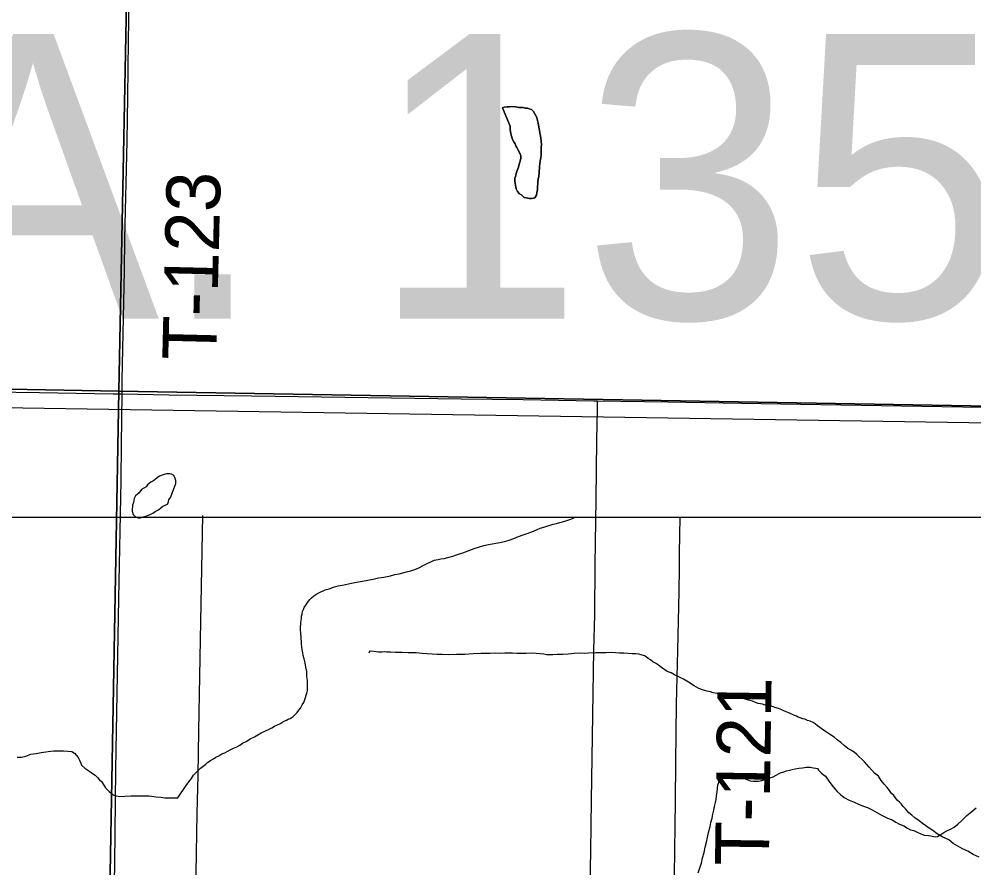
# Model space of a CAD drawing. Extents: x 2.4 to 73.1, y 4.5 to 25.6.
# Drawn here: x 43.971 to 44.474, y 19.357 to 19.804 of the extents above; entities that cross this region are included whole.
import ezdxf

# ---------------------------------------------------------------- set-up
doc = ezdxf.new("R2010")
doc.units = 0
for name, color, linetype in [('GM_X_County_Road', 7, 'Continuous'), ('GM_X_Minor_Lake', 7, 'Continuous'), ('GM_X_Minor_River', 7, 'Continuous'), ('GM_X_Section', 7, 'Continuous'), ('GM_X_State_Route', 7, 'Continuous'), ('GM_X_Township_Road', 7, 'Continuous'), ('GM_X_Township_Road_Text', 7, 'Continuous'), ('SH_Text', 7, 'Continuous')]:
    doc.layers.add(name, color=color, linetype=linetype)

msp = doc.modelspace()

# ---------------------------------------------------------------- linework, layer by layer
at = {"layer": 'GM_X_County_Road'}
msp.add_lwpolyline([(44.01702, 19.10105), (44.01746, 19.1365), (44.01805, 19.15825), (44.01831, 19.1769), (44.01926, 19.22506), (44.01963, 19.24681), (44.02, 19.27167), (44.02064, 19.3043), (44.02109, 19.33071), (44.02153, 19.35868), (44.02219, 19.40841), (44.02378, 19.49852), (44.02492, 19.56067), (44.02516, 19.57932), (44.02545, 19.60622)], dxfattribs=at)
at = {"layer": 'GM_X_Minor_Lake'}
for points in [[(44.24431, 19.71562), (44.24453, 19.71676), (44.24456, 19.71809), (44.24459, 19.71942), (44.24501, 19.72093), (44.24523, 19.72244), (44.24526, 19.72377), (44.24529, 19.72491), (44.24531, 19.72605), (44.24553, 19.72737), (44.24576, 19.72908), (44.24599, 19.73059), (44.24621, 19.73192), (44.24624, 19.73324), (44.24627, 19.73476), (44.2463, 19.73609), (44.24634, 19.73761), (44.24618, 19.73932), (44.24603, 19.74103), (44.2457, 19.74294), (44.24469, 19.74885), (44.24434, 19.75019), (44.24417, 19.75114), (44.24381, 19.7521), (44.24308, 19.75345), (44.24217, 19.75499), (44.24124, 19.75596), (44.23992, 19.75637), (44.23898, 19.75677), (44.23784, 19.75679), (44.2367, 19.75701), (44.23442, 19.75706), (44.23272, 19.75748), (44.23063, 19.75753), (44.22948, 19.75736), (44.22834, 19.75739), (44.22682, 19.75723), (44.22586, 19.75687)], [(44.22586, 19.75687), (44.22682, 19.75723), (44.22834, 19.75739), (44.22948, 19.75736), (44.23063, 19.75753), (44.23272, 19.75748), (44.23442, 19.75706), (44.2367, 19.75701), (44.23784, 19.75679), (44.23898, 19.75677), (44.23992, 19.75637), (44.24124, 19.75596), (44.24217, 19.75499), (44.24308, 19.75345), (44.24381, 19.7521), (44.24417, 19.75114), (44.24434, 19.75019), (44.24469, 19.74885), (44.2457, 19.74294), (44.24603, 19.74103), (44.24618, 19.73932), (44.24634, 19.73761), (44.2463, 19.73609), (44.24627, 19.73476), (44.24624, 19.73324), (44.24621, 19.73192), (44.24599, 19.73059), (44.24576, 19.72908), (44.24553, 19.72737), (44.24531, 19.72605), (44.24529, 19.72491), (44.24526, 19.72377), (44.24523, 19.72244), (44.24501, 19.72093), (44.24459, 19.71942), (44.24456, 19.71809), (44.24453, 19.71676), (44.24431, 19.71562), (44.24428, 19.71392), (44.24405, 19.7124), (44.24383, 19.71089), (44.24285, 19.70958), (44.24113, 19.70924), (44.24017, 19.70907), (44.23828, 19.70949), (44.23734, 19.7097), (44.23603, 19.71087), (44.23491, 19.71166), (44.2338, 19.71282), (44.23307, 19.71417), (44.2329, 19.71512), (44.2324, 19.71836), (44.23243, 19.71988), (44.23265, 19.72083), (44.23306, 19.72215), (44.23327, 19.72309), (44.23388, 19.72479), (44.23428, 19.72573), (44.23469, 19.72724), (44.23511, 19.72875), (44.23553, 19.73045), (44.23555, 19.73158), (44.23502, 19.73312), (44.23392, 19.73504), (44.23337, 19.736), (44.23282, 19.73696), (44.23246, 19.73792), (44.23192, 19.73907), (44.23119, 19.74023), (44.23083, 19.74138), (44.23048, 19.74253), (44.23031, 19.74348), (44.22997, 19.74538), (44.22999, 19.74633), (44.22983, 19.74729), (44.22586, 19.75687)], [(44.22586, 19.75687), (44.22983, 19.74729), (44.22999, 19.74633), (44.22997, 19.74538), (44.23031, 19.74348), (44.23048, 19.74253), (44.23083, 19.74138), (44.23119, 19.74023), (44.23192, 19.73907), (44.23246, 19.73792), (44.23282, 19.73696), (44.23337, 19.736), (44.23392, 19.73504), (44.23502, 19.73312), (44.23555, 19.73158), (44.23553, 19.73045), (44.23511, 19.72875), (44.23469, 19.72724), (44.23428, 19.72573), (44.23388, 19.72479), (44.23327, 19.72309), (44.23306, 19.72215), (44.23265, 19.72083), (44.23243, 19.71988), (44.2324, 19.71836), (44.2329, 19.71512), (44.23307, 19.71417), (44.2338, 19.71282), (44.23491, 19.71166), (44.23603, 19.71087), (44.23734, 19.7097), (44.23828, 19.70949), (44.24017, 19.70907), (44.24113, 19.70924), (44.24285, 19.70958), (44.24383, 19.71089), (44.24405, 19.7124), (44.24428, 19.71392), (44.24431, 19.71562)], [(44.04944, 19.54814), (44.04964, 19.54871), (44.05006, 19.55041), (44.05085, 19.55172), (44.05165, 19.55341), (44.05206, 19.55454), (44.05266, 19.55624), (44.05326, 19.55755), (44.05368, 19.55906), (44.05371, 19.56058), (44.05336, 19.56173), (44.05264, 19.56326), (44.05151, 19.56386), (44.05056, 19.56407), (44.04904, 19.5641), (44.04809, 19.56394), (44.04655, 19.5634), (44.04521, 19.56286), (44.04386, 19.56194), (44.0427, 19.56102), (44.04154, 19.56029), (44.04058, 19.55974), (44.03883, 19.55826), (44.03805, 19.55733), (44.03689, 19.55659), (44.03574, 19.55586), (44.03417, 19.55399), (44.03243, 19.55252), (44.03183, 19.5512), (44.0314, 19.54893), (44.03099, 19.54761), (44.03096, 19.54666), (44.03075, 19.54572), (44.03072, 19.54439), (44.03125, 19.54267), (44.03274, 19.5413), (44.03406, 19.54089), (44.03501, 19.54087), (44.03674, 19.5414), (44.03789, 19.54176), (44.03942, 19.54229), (44.04057, 19.54284), (44.04154, 19.54338), (44.04289, 19.5443), (44.04462, 19.54521), (44.04578, 19.54614), (44.04694, 19.54706), (44.04944, 19.54814)], [(44.04944, 19.54814), (44.04964, 19.54871), (44.05006, 19.55041), (44.05085, 19.55172), (44.05165, 19.55341), (44.05206, 19.55454), (44.05266, 19.55624), (44.05326, 19.55755), (44.05368, 19.55906), (44.05371, 19.56058), (44.05336, 19.56173), (44.05264, 19.56326), (44.05151, 19.56386), (44.05056, 19.56407), (44.04904, 19.5641), (44.04809, 19.56394), (44.04655, 19.5634), (44.04521, 19.56286), (44.04386, 19.56194), (44.0427, 19.56102), (44.04154, 19.56029), (44.04058, 19.55974), (44.03883, 19.55826), (44.03805, 19.55733)], [(44.03805, 19.55733), (44.03689, 19.55659), (44.03574, 19.55586), (44.03417, 19.55399), (44.03243, 19.55252), (44.03183, 19.5512), (44.0314, 19.54893), (44.03099, 19.54761), (44.03096, 19.54666), (44.03075, 19.54572), (44.03072, 19.54439), (44.03125, 19.54267), (44.03274, 19.5413), (44.03406, 19.54089), (44.03501, 19.54087), (44.03674, 19.5414), (44.03789, 19.54176), (44.03942, 19.54229), (44.04057, 19.54284), (44.04154, 19.54338), (44.04289, 19.5443), (44.04462, 19.54521), (44.04578, 19.54614), (44.04694, 19.54706), (44.04944, 19.54814)]]:
    msp.add_lwpolyline(points, dxfattribs=at)
at = {"layer": 'GM_X_Minor_River'}
for points in [[(44.77523, 19.34174), (44.77748, 19.58625), (42.99849, 19.61388)], [(44.25604, 19.53844), (44.25757, 19.53878), (44.25929, 19.53932), (44.26082, 19.53985), (44.26274, 19.54057), (44.26385, 19.54109), (44.26385, 19.54109)], [(44.11396, 19.4353), (44.11551, 19.43621), (44.11687, 19.43751), (44.11765, 19.43844), (44.11862, 19.43956), (44.11941, 19.44068), (44.1204, 19.44237), (44.12119, 19.44368), (44.12179, 19.44519), (44.12282, 19.44858), (44.12304, 19.44991), (44.12308, 19.45161), (44.12312, 19.45332), (44.12316, 19.45522), (44.12283, 19.45732), (44.1227, 19.45998), (44.12218, 19.46227), (44.12185, 19.46456), (44.12133, 19.46666), (44.1208, 19.46838), (44.12064, 19.4699), (44.1203, 19.47162), (44.12014, 19.47295), (44.11999, 19.47447), (44.12002, 19.4758), (44.11986, 19.47733), (44.1197, 19.47847), (44.11953, 19.47961), (44.11956, 19.48056), (44.11939, 19.48151), (44.11944, 19.4836), (44.11965, 19.48474), (44.11968, 19.48588), (44.1197, 19.48682), (44.11992, 19.48796), (44.11994, 19.4891), (44.12035, 19.49023), (44.12057, 19.49155), (44.12097, 19.49268), (44.12138, 19.49362), (44.12217, 19.49494), (44.12295, 19.49606), (44.12373, 19.49699), (44.12432, 19.49793), (44.1253, 19.49885), (44.12646, 19.49978), (44.128, 19.50088), (44.12916, 19.50143), (44.13243, 19.50306), (44.13453, 19.50358), (44.13683, 19.50448), (44.13932, 19.50518), (44.14237, 19.50568), (44.14543, 19.50637), (44.14887, 19.50706), (44.15211, 19.50755), (44.15497, 19.50806), (44.15765, 19.50857), (44.16051, 19.50926), (44.16338, 19.50977), (44.16681, 19.51045), (44.16911, 19.51116), (44.1714, 19.51148), (44.17331, 19.51201), (44.17523, 19.51254), (44.17752, 19.51306), (44.17963, 19.51377), (44.18174, 19.51467), (44.18404, 19.51576), (44.18616, 19.51685), (44.18808, 19.51775), (44.18981, 19.51867), (44.19191, 19.519), (44.19344, 19.51934), (44.19515, 19.51949), (44.19707, 19.52002), (44.19974, 19.52072), (44.20224, 19.52161), (44.20492, 19.5225), (44.2078, 19.52358), (44.21086, 19.52484), (44.21374, 19.52572), (44.21603, 19.52643), (44.21852, 19.52694), (44.22043, 19.52728), (44.22233, 19.52762), (44.22443, 19.52795), (44.22692, 19.52846), (44.2294, 19.52917), (44.2319, 19.53006), (44.23439, 19.53114), (44.23669, 19.53204), (44.2388, 19.53275), (44.24072, 19.53347), (44.24225, 19.534), (44.24417, 19.53472), (44.24571, 19.53545), (44.24762, 19.53597), (44.2526, 19.53757), (44.25432, 19.53791), (44.25604, 19.53844)], [(44.27769, 19.46988), (44.27502, 19.46975), (44.27122, 19.46965), (44.26893, 19.46951), (44.26646, 19.46957), (44.26361, 19.46944), (44.26056, 19.46913), (44.25771, 19.469), (44.25466, 19.46888), (44.25238, 19.46874), (44.25067, 19.46878), (44.24914, 19.46882), (44.24763, 19.46904), (44.24573, 19.46927), (44.24365, 19.46951), (44.24099, 19.46957), (44.23832, 19.46944), (44.23566, 19.4695), (44.23338, 19.46955), (44.2311, 19.4696), (44.2292, 19.46965), (44.22711, 19.46969), (44.22483, 19.46955), (44.22236, 19.46961), (44.21931, 19.46949), (44.21437, 19.46941), (44.21037, 19.46931), (44.206, 19.46903), (44.20162, 19.46894), (44.19744, 19.46884), (44.19402, 19.46892), (44.19136, 19.46898), (44.18357, 19.46953), (44.18035, 19.4698), (44.17617, 19.46989), (44.17294, 19.46996), (44.16952, 19.47004), (44.16686, 19.4701), (44.16477, 19.47015), (44.16363, 19.47036), (44.16249, 19.4702), (44.16059, 19.47024), (44.15812, 19.47049), (44.15623, 19.47072), (44.15585, 19.47073), (44.15584, 19.47054), (44.15584, 19.47054), (44.15544, 19.4696)], [(44.44767, 19.37965), (44.44543, 19.38141), (44.44318, 19.38298), (44.4415, 19.38434), (44.44001, 19.38552), (44.43909, 19.38668), (44.43816, 19.38765), (44.43705, 19.38881), (44.43613, 19.39016), (44.43501, 19.39114), (44.43389, 19.3923), (44.43297, 19.39346), (44.43204, 19.39462), (44.43093, 19.39579), (44.42983, 19.39733), (44.42853, 19.39888), (44.42705, 19.40062), (44.42538, 19.40256), (44.42391, 19.40487), (44.42186, 19.40644), (44.42056, 19.40798), (44.41908, 19.40954), (44.41778, 19.41108), (44.41667, 19.41244), (44.41537, 19.41361), (44.41388, 19.41497), (44.41258, 19.41633), (44.41109, 19.4175), (44.4094, 19.41849), (44.4079, 19.41947), (44.40584, 19.42104), (44.40417, 19.4226), (44.4023, 19.42397), (44.40062, 19.42533), (44.39875, 19.42671), (44.39706, 19.42769), (44.39556, 19.42868), (44.39182, 19.43142), (44.3907, 19.43239), (44.38958, 19.43318), (44.38807, 19.43378), (44.38656, 19.4342), (44.38525, 19.4348), (44.38411, 19.43501), (44.38279, 19.43561), (44.38166, 19.43602), (44.38072, 19.43642), (44.37978, 19.43682), (44.37865, 19.43741), (44.37752, 19.43782), (44.3762, 19.43842), (44.37451, 19.43903), (44.373, 19.43982), (44.37131, 19.44043), (44.36942, 19.44104), (44.36753, 19.44165), (44.36583, 19.44188), (44.36432, 19.44229), (44.3628, 19.44271), (44.36186, 19.44292), (44.36053, 19.44314), (44.35922, 19.44374), (44.35752, 19.44435), (44.35544, 19.44496), (44.35317, 19.44558), (44.35034, 19.44641), (44.34751, 19.44723), (44.34448, 19.44768), (44.34163, 19.44793), (44.33879, 19.44838), (44.3369, 19.4488), (44.33539, 19.44921), (44.33369, 19.44963), (44.3318, 19.45024), (44.32935, 19.45106), (44.32691, 19.45244), (44.32391, 19.45441), (44.32128, 19.45599), (44.31884, 19.45718), (44.31658, 19.45818), (44.31471, 19.45936), (44.31263, 19.45998), (44.30964, 19.46214), (44.30814, 19.46331), (44.30646, 19.4643), (44.30514, 19.46509), (44.30383, 19.46606), (44.30271, 19.46685), (44.30159, 19.46763), (44.30065, 19.46823), (44.29895, 19.46883), (44.29763, 19.46905), (44.29611, 19.46928), (44.29421, 19.46932), (44.29213, 19.46956), (44.28985, 19.46961), (44.28757, 19.46966), (44.28548, 19.4699), (44.2832, 19.46995), (44.28035, 19.46982), (44.27769, 19.46988)], [(43.97016, 19.41481), (43.97244, 19.41495), (43.97474, 19.41547), (43.97742, 19.41636), (43.98009, 19.41686), (43.98276, 19.41737), (43.98639, 19.41786), (43.98925, 19.41818), (43.99191, 19.41812), (43.99457, 19.41825), (43.99685, 19.418), (43.99893, 19.41777), (44.00043, 19.41697), (44.00136, 19.41581), (44.00228, 19.41465), (44.00301, 19.41331), (44.00355, 19.41197), (44.00409, 19.41062), (44.00577, 19.40907), (44.00689, 19.40828), (44.00839, 19.4073), (44.00989, 19.40632), (44.0112, 19.40534), (44.0125, 19.40417), (44.01361, 19.403), (44.01454, 19.40203), (44.01583, 19.4001), (44.01675, 19.39875), (44.01749, 19.39779), (44.01861, 19.39681), (44.01973, 19.39584), (44.02103, 19.39486), (44.02235, 19.39445), (44.02425, 19.39421), (44.02692, 19.39434), (44.02996, 19.39446), (44.03338, 19.39458), (44.03661, 19.39451), (44.03965, 19.39444), (44.04345, 19.39397), (44.04591, 19.39372), (44.048, 19.39349), (44.0499, 19.39344), (44.05199, 19.3934), (44.0537, 19.39336), (44.05484, 19.39352), (44.05622, 19.39558), (44.05779, 19.39782), (44.05917, 19.39988), (44.06055, 19.40194), (44.06192, 19.40362), (44.06309, 19.4053), (44.06426, 19.4066), (44.06543, 19.40791), (44.06679, 19.40902), (44.06815, 19.41012), (44.0695, 19.41123), (44.07066, 19.41216), (44.07202, 19.41308), (44.07356, 19.41399), (44.07491, 19.41491), (44.07645, 19.41563), (44.07799, 19.41655), (44.07952, 19.41708), (44.08087, 19.41781), (44.08241, 19.41873), (44.08414, 19.41964), (44.08587, 19.42036), (44.08741, 19.42127), (44.08895, 19.42219), (44.09107, 19.42328), (44.093, 19.42457), (44.09512, 19.42566), (44.09704, 19.42656), (44.09877, 19.42766), (44.10069, 19.42857), (44.10262, 19.42948), (44.10435, 19.43039), (44.10569, 19.43112), (44.10723, 19.43184), (44.10858, 19.43238), (44.10954, 19.43312), (44.11089, 19.43385), (44.11204, 19.43439), (44.11301, 19.43494), (44.11396, 19.4353)], [(44.32902, 19.3539), (44.32984, 19.35654), (44.33066, 19.35899), (44.33129, 19.36183), (44.33212, 19.36466), (44.33275, 19.36749), (44.33338, 19.37014), (44.33382, 19.3726), (44.33445, 19.37524), (44.33528, 19.37826), (44.33571, 19.38053), (44.33633, 19.38279), (44.33676, 19.38487), (44.33719, 19.38695), (44.33761, 19.38884), (44.33804, 19.39092), (44.33846, 19.39262), (44.33869, 19.39452), (44.33893, 19.3966), (44.33916, 19.3983), (44.33939, 19.4002), (44.3398, 19.40171), (44.34003, 19.40322), (44.34043, 19.40435), (44.34141, 19.40547), (44.34294, 19.40601), (44.34389, 19.40579), (44.34522, 19.40557), (44.34654, 19.40536), (44.34787, 19.40514), (44.349, 19.40492), (44.35032, 19.40451), (44.35165, 19.4041), (44.35316, 19.40369), (44.35466, 19.40308), (44.35636, 19.40247), (44.35788, 19.40225), (44.3594, 19.40222), (44.36073, 19.40219), (44.36244, 19.40253), (44.36417, 19.40306), (44.36589, 19.40359), (44.36742, 19.40412), (44.36857, 19.40448), (44.37011, 19.40539), (44.37127, 19.40613), (44.37242, 19.40667), (44.37415, 19.4072), (44.37549, 19.40774), (44.37702, 19.40809), (44.37855, 19.40843), (44.38008, 19.40878)], [(44.38008, 19.40878), (44.38199, 19.40911), (44.38389, 19.40926), (44.38599, 19.40959), (44.38808, 19.40954), (44.38959, 19.40932), (44.39092, 19.4091), (44.39187, 19.40889), (44.39241, 19.40793), (44.39371, 19.40657), (44.39484, 19.40578), (44.39615, 19.4048), (44.39743, 19.40269), (44.40001, 19.3994), (44.40094, 19.39824), (44.40223, 19.39669), (44.40391, 19.39513), (44.40597, 19.39357), (44.40859, 19.39218), (44.41123, 19.39117), (44.41349, 19.39017), (44.41556, 19.38917), (44.4182, 19.38835), (44.42065, 19.38716), (44.42309, 19.38578), (44.4259, 19.38419), (44.42872, 19.3828), (44.43117, 19.3818), (44.43305, 19.38061), (44.43511, 19.37962), (44.43737, 19.37862), (44.43925, 19.37743), (44.44094, 19.37664), (44.44264, 19.37622), (44.44433, 19.37542), (44.44603, 19.37462), (44.4481, 19.37382), (44.45037, 19.37358), (44.45151, 19.37336), (44.45378, 19.37293), (44.45512, 19.37309), (44.45685, 19.37419), (44.45839, 19.3751), (44.45994, 19.37602), (44.46186, 19.37693), (44.46378, 19.37802), (44.46572, 19.3795), (44.46785, 19.38154), (44.47058, 19.38413), (44.47309, 19.38617), (44.47542, 19.3882)], [(44.47712, 19.36227), (44.47392, 19.36367), (44.4711, 19.36526), (44.46828, 19.36665), (44.46585, 19.36803), (44.46341, 19.36942), (44.46098, 19.37137), (44.45759, 19.37297), (44.45497, 19.37455), (44.45254, 19.37631), (44.4501, 19.37788), (44.44767, 19.37965)]]:
    msp.add_lwpolyline(points, dxfattribs=at)
at = {"layer": 'GM_X_Section'}
for points in [[(44.03361, 20.1068), (44.02369, 19.60768), (43.52171, 19.61671), (43.53362, 20.112)], [(44.03361, 20.1068), (44.53042, 20.10376), (44.52379, 19.59907), (44.02369, 19.60768)], [(44.02369, 19.60768), (44.01453, 19.09983), (43.51203, 19.10261), (43.52171, 19.61671)], [(44.52379, 19.59907), (44.51738, 19.09589), (44.01453, 19.09983), (44.02369, 19.60768)]]:
    msp.add_lwpolyline(points, close=True, dxfattribs=at)
at = {"layer": 'GM_X_State_Route'}
msp.add_lwpolyline([(43.8948, 19.60821), (43.98184, 19.60691), (44.0207, 19.60632), (44.02545, 19.60622), (44.05024, 19.6058), (44.09376, 19.60524), (44.20411, 19.60358), (44.23676, 19.60319), (44.27406, 19.60261), (44.276, 19.60258), (44.31292, 19.60197), (44.35178, 19.6013), (44.38286, 19.60077), (44.44659, 19.59971), (44.49011, 19.59908)], dxfattribs=at)
at = {"layer": 'GM_X_Township_Road'}
for points in [[(44.02545, 19.60622), (44.02552, 19.61349), (44.02667, 19.67098), (44.02688, 19.68807), (44.02818, 19.73933), (44.02849, 19.76264), (44.02887, 19.79217), (44.02959, 19.83412), (44.0305, 19.88073), (44.03095, 19.91025), (44.03271, 20.00347), (44.03321, 20.03144), (44.03358, 20.04853), (44.0341, 20.0796), (44.03427, 20.09358), (44.03454, 20.10591)], [(44.26821, 19.09825), (44.26827, 19.10138), (44.26853, 19.11536), (44.26909, 19.14955), (44.26925, 19.17287), (44.27002, 19.21483), (44.27022, 19.22726), (44.27014, 19.24436), (44.27028, 19.26145), (44.2707, 19.28787), (44.27105, 19.29875), (44.2716, 19.31273), (44.27211, 19.34692), (44.27245, 19.36557), (44.27282, 19.392), (44.27348, 19.43708), (44.27404, 19.47127), (44.27444, 19.48992), (44.27475, 19.51635), (44.2752, 19.55054), (44.27556, 19.58163), (44.2759, 19.59873), (44.27594, 19.60028), (44.276, 19.60258)], [(44.06396, 19.32634), (44.06427, 19.34328), (44.06506, 19.38525), (44.06548, 19.40545), (44.06588, 19.42877), (44.067, 19.48627), (44.06791, 19.54223)], [(44.31266, 19.32483), (44.31347, 19.32808), (44.31385, 19.32959), (44.3149, 19.33413), (44.31559, 19.33875), (44.316, 19.34339), (44.31643, 19.35272), (44.3171, 19.39162), (44.31723, 19.41185), (44.31759, 19.44296), (44.31827, 19.47097), (44.31898, 19.50208), (44.31917, 19.51452), (44.31922, 19.5223), (44.31946, 19.54109)]]:
    msp.add_lwpolyline(points, dxfattribs=at)
at = {"layer": 'SH_Text'}
msp.add_lwpolyline([(45.17346, 19.54109), (43.56201, 19.54109), (43.56201, 20.16526), (45.17346, 20.16526)], close=True, dxfattribs=at)

# ---------------------------------------------------------------- texts
at = {"layer": 'GM_X_Township_Road_Text'}
for s, rotation, p in [('T-123', 88.5955, (44.07498, 19.62373)), ('T-121', 89.1592, (44.36621, 19.35757))]:
    msp.add_text(s, height=0.028409, rotation=rotation, dxfattribs=at).set_placement(p)
at = {"layer": 'SH_Text'}
msp.add_text('STA. 1350+00', height=0.1499997, rotation=360, dxfattribs=at).set_placement((43.65505, 19.64584))

doc.saveas('drawing.dxf')
